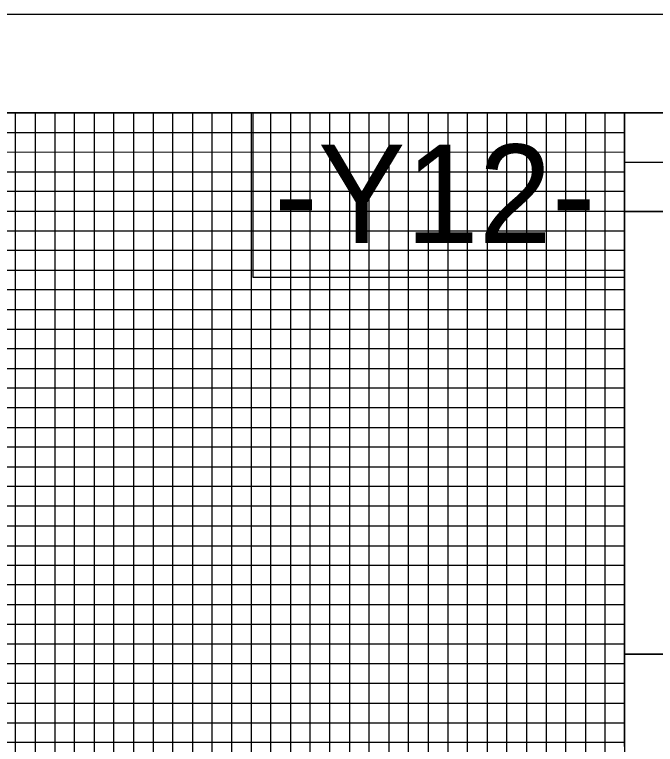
# Model space of a CAD drawing. Extents: x 502400 to 509344, y 448070 to 484209.
# Drawn here: x 506913.9 to 507076.9, y 484023.2 to 484208.7 of the extents above; entities that cross this region are included whole.
import ezdxf

# ---------------------------------------------------------------- set-up
doc = ezdxf.new("R2010")
doc.units = 0
for name, color, linetype in [('Old_Level_1', 7, 'Continuous'), ('Prop Grid Mask', 7, 'Continuous'), ('Sheet Layout Profile Border Port 1', 7, 'Continuous'), ('Sheet Plot Border Outside CELL', 7, 'Continuous'), ('Sheet Profile CELL', 7, 'Continuous'), ('Sheet Profile Grid Major CELL', 7, 'Continuous'), ('Sheet Profile Grid Middle CELL', 7, 'Continuous'), ('Sheet Profile Grid Minor CELL', 7, 'Continuous'), ('Sheet Sticker Exception Certification CELL', 7, 'Continuous')]:
    doc.layers.add(name, color=color, linetype=linetype)

msp = doc.modelspace()

# ---------------------------------------------------------------- linework, layer by layer
at = {"layer": 'Prop Grid Mask'}
msp.add_lwpolyline([(507069.03, 484183.71), (506974.48, 484183.71), (506974.48, 484142), (507069.03, 484142)], close=True, dxfattribs=at)
at = {"layer": 'Sheet Layout Profile Border Port 1'}
msp.add_lwpolyline([(506419.08, 484183.71), (507169.08, 484183.71), (507169.08, 483683.71), (506419.08, 483683.71)], close=True, dxfattribs=at)
at = {"layer": 'Sheet Plot Border Outside CELL'}
msp.add_lwpolyline([(505602.08, 483108.71), (507286.08, 483108.71), (507286.08, 484208.71), (505602.08, 484208.71)], close=True, dxfattribs=at)
at = {"layer": 'Sheet Profile CELL'}
msp.add_line((507069.03, 484171.16), (507269.08, 484171.16), dxfattribs=at)
for points in [[(507269.08, 484183.71), (505769.08, 484183.71), (505769.08, 483133.71), (507269.08, 483133.71)], [(507069.03, 484183.71), (507269.08, 484183.71), (507269.08, 484158.66), (507069.03, 484158.66)], [(507069.03, 484158.66), (507169.08, 484158.66), (507169.08, 484046.16), (507069.03, 484046.16)]]:
    msp.add_lwpolyline(points, close=True, dxfattribs=at)
at = {"layer": 'Sheet Profile Grid Major CELL'}
for points in [[(506519.08, 483683.71), (506569.08, 483683.71), (506569.08, 484183.71), (506619.08, 484183.71), (506619.08, 483683.71), (506669.08, 483683.71), (506669.08, 484183.71), (506719.08, 484183.71), (506719.08, 483683.71), (506769.08, 483683.71), (506769.08, 484183.71), (506819.08, 484183.71), (506819.08, 483683.71), (506869.08, 483683.71), (506869.08, 484183.71), (506919.08, 484183.71), (506919.08, 483683.71), (506969.08, 483683.71), (506969.08, 484183.71), (507019.08, 484183.71), (507019.08, 483683.71), (507069.08, 483683.71), (507069.08, 484183.71), (507095.38, 484183.71)], [(505769.08, 484133.71), (507069.08, 484133.71)], [(507069.08, 484083.71), (505769.08, 484083.71), (505769.08, 484033.71), (507069.08, 484033.71)]]:
    msp.add_lwpolyline(points, dxfattribs=at)
at = {"layer": 'Sheet Profile Grid Middle CELL'}
msp.add_line((505769.08, 484158.71), (507069.03, 484158.71), dxfattribs=at)
msp.add_line((505769.08, 484158.71), (507069.03, 484158.71), dxfattribs=at)
for points in [[(506894.08, 484183.71), (506944.08, 484183.71), (506944.08, 483683.71), (506994.08, 483683.71), (506994.08, 484183.71), (507044.08, 484183.71), (507044.08, 483683.71), (507094.08, 483683.71), (507094.08, 484022.66)], [(507069.08, 484108.71), (505769.08, 484108.71), (505769.08, 484058.71), (507069.08, 484058.71)]]:
    msp.add_lwpolyline(points, dxfattribs=at)
at = {"layer": 'Sheet Profile Grid Minor CELL'}
for p, q in [((505819.08, 484178.71), (507069.08, 484178.71)), ((507069.08, 484173.71), (505819.08, 484173.36)), ((505819.08, 484168.71), (507069.08, 484168.71)), ((507069.03, 484048.71), (505819.08, 484048.71)), ((507069.08, 484043.71), (505819.08, 484043.71)), ((507069.08, 484038.71), (505819.08, 484038.71)), ((505819.08, 484028.71), (507069.08, 484028.71)), ((507069.08, 484023.71), (505819.08, 484023.71))]:
    msp.add_line(p, q, dxfattribs=at)
for points in [[(506909.08, 483683.71), (506914.08, 483683.71), (506914.08, 484183.71), (506924.08, 484183.71), (506924.08, 483683.71), (506929.08, 483683.71), (506929.08, 484183.71), (506934.08, 484183.71), (506934.08, 483683.71), (506939.08, 483683.71), (506939.08, 484183.71), (506949.08, 484183.71), (506949.08, 483683.71), (506954.08, 483683.71), (506954.08, 484183.71), (506959.08, 484183.71), (506959.08, 483683.71)], [(506964.08, 483683.71), (506964.08, 484183.71), (506974.08, 484183.71), (506974.08, 483683.71)], [(506979.08, 483683.71), (506979.08, 484183.71), (506984.08, 484183.71), (506984.08, 483683.71)], [(506989.08, 483683.71), (506989.08, 484183.71), (506999.08, 484183.71), (506999.08, 483683.71)], [(507004.08, 483683.71), (507004.08, 484183.71), (507009.08, 484183.71), (507009.08, 483683.71)], [(507014.08, 483683.71), (507014.08, 484183.71), (507024.08, 484183.71), (507024.08, 483683.71)], [(507029.08, 483683.71), (507029.08, 484183.71), (507034.08, 484183.71), (507034.08, 483683.71)], [(507039.08, 483683.71), (507039.08, 484183.71), (507049.08, 484183.71), (507049.08, 483683.71)], [(507054.08, 483683.71), (507054.08, 484183.71), (507059.08, 484183.71), (507059.08, 483683.71)], [(507064.08, 483683.71), (507064.08, 484183.71), (507074.08, 484183.71)], [(507069.08, 484163.71), (505819.08, 484163.71), (505819.08, 484153.71), (507069.08, 484153.71)], [(507069.03, 484148.71), (505819.08, 484148.71), (505819.08, 484143.71), (507069.08, 484143.71)], [(507069.08, 484138.71), (505819.08, 484138.71), (505819.08, 484128.71), (507069.08, 484128.71)], [(507069.08, 484123.71), (505819.08, 484123.71), (505819.08, 484118.71), (507069.08, 484118.71)], [(507069.08, 484113.71), (505819.08, 484113.71), (505819.08, 484103.71), (507069.08, 484103.71)], [(507069.08, 484098.71), (505819.08, 484098.71), (505819.08, 484093.71), (507069.08, 484093.71)], [(507069.08, 484088.71), (505819.08, 484088.71), (505819.08, 484078.71), (507069.08, 484078.71)], [(507069.08, 484073.61), (505819.18, 484073.61), (505819.18, 484068.71), (507069.08, 484068.71)], [(507069.08, 484063.71), (505819.08, 484063.71), (505819.08, 484053.71), (507069.08, 484053.71)]]:
    msp.add_lwpolyline(points, dxfattribs=at)
at = {"layer": 'Sheet Sticker Exception Certification CELL'}
for p, q in [((507069.03, 484022.66), (507069.03, 484046.16)), ((507069.03, 484046.16), (507269.07, 484046.16)), ((507069.03, 484022.66), (507069.03, 484046.16)), ((507069.03, 484046.16), (507269.07, 484046.16))]:
    msp.add_line(p, q, dxfattribs=at)

# ---------------------------------------------------------------- texts
at = {"layer": 'Old_Level_1'}
msp.add_text('-Y12-', height=25, dxfattribs=at).set_placement((506979.88, 484150.68))

doc.saveas('drawing.dxf')
